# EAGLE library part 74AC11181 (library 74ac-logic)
ALU/FUNCTION GENERATOR
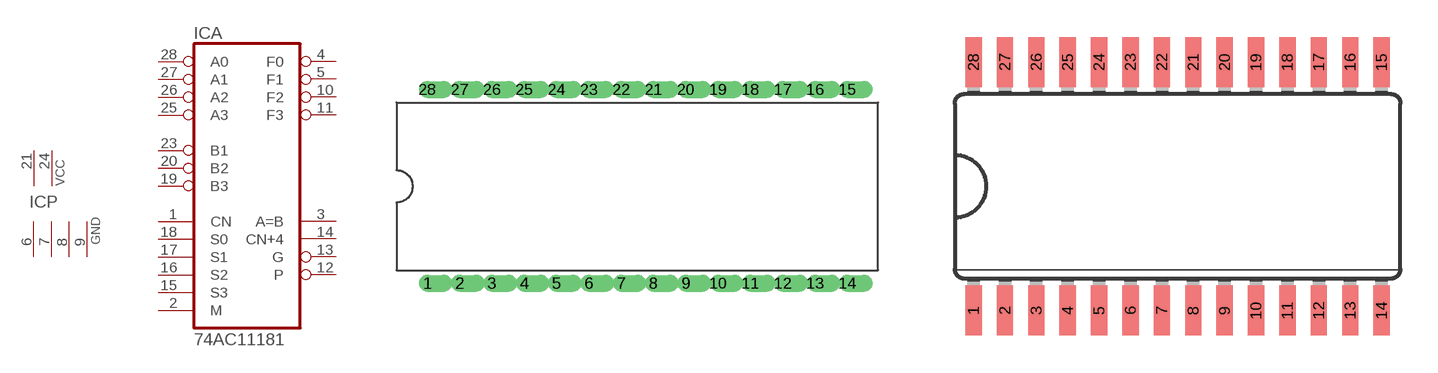
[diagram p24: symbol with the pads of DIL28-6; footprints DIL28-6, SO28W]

Designator prefix IC; gates A=7411181 P=2PWR4GND

## 74AC11181  [DIL28-6]
1  A:CN  in
2  A:M  in
3  A:A=B  out
4  A:F0  out
5  A:F1  out
6  P:GND  pwr
7  P:GND  pwr
8  P:GND  pwr
9  P:GND  pwr
10  A:F2  out
11  A:F3  out
12  A:P  out
13  A:G  out
14  A:CN+4  out
15  A:S3  in
16  A:S2  in
17  A:S1  in
18  A:S0  in
19  A:B3  in
20  A:B2  in
21  P:VCC  pwr
23  A:B1  in
24  P:VCC  pwr
25  A:A3  in
26  A:A2  in
27  A:A1  in
28  A:A0  in

## 74AC11181D  [SO28W]
Pads as for DIL28-6

## Footprint DIL28-6 (pad centres in mm)
Dual In Line 0.6 inch
drill 0.813 offset: 1 -16.51,-7.62; 2 -13.97,-7.62; 3 -11.43,-7.62; 4 -8.89,-7.62; 5 -6.35,-7.62; 6 -3.81,-7.62; 7 -1.27,-7.62; 8 1.27,-7.62; 9 3.81,-7.62; 10 6.35,-7.62; 11 8.89,-7.62; 12 11.43,-7.62; 13 13.97,-7.62; 14 16.51,-7.62; 15 16.51,7.62; 16 13.97,7.62; 17 11.43,7.62; 18 8.89,7.62; 19 6.35,7.62; 20 3.81,7.62; 21 1.27,7.62; 22 -1.27,7.62; 23 -3.81,7.62; 24 -6.35,7.62; 25 -8.89,7.62; 26 -11.43,7.62; 27 -13.97,7.62; 28 -16.51,7.62

## Footprint SO28W (pad centres in mm)
Wide Small Outline package 300 mil
smd 0.66 x 2.032: 1 -8.255,-5.029; 2 -6.985,-5.029; 3 -5.715,-5.029; 4 -4.445,-5.029; 5 -3.175,-5.029; 6 -1.905,-5.029; 7 -0.635,-5.029; 8 0.635,-5.029; 9 1.905,-5.029; 10 3.175,-5.029; 11 4.445,-5.029; 12 5.715,-5.029; 13 6.985,-5.029; 14 8.255,-5.029; 15 8.255,5.029; 16 6.985,5.029; 17 5.715,5.029; 18 4.445,5.029; 19 3.175,5.029; 20 1.905,5.029; 21 0.635,5.029; 22 -0.635,5.029; 23 -1.905,5.029; 24 -3.175,5.029; 25 -4.445,5.029; 26 -5.715,5.029; 27 -6.985,5.029; 28 -8.255,5.029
